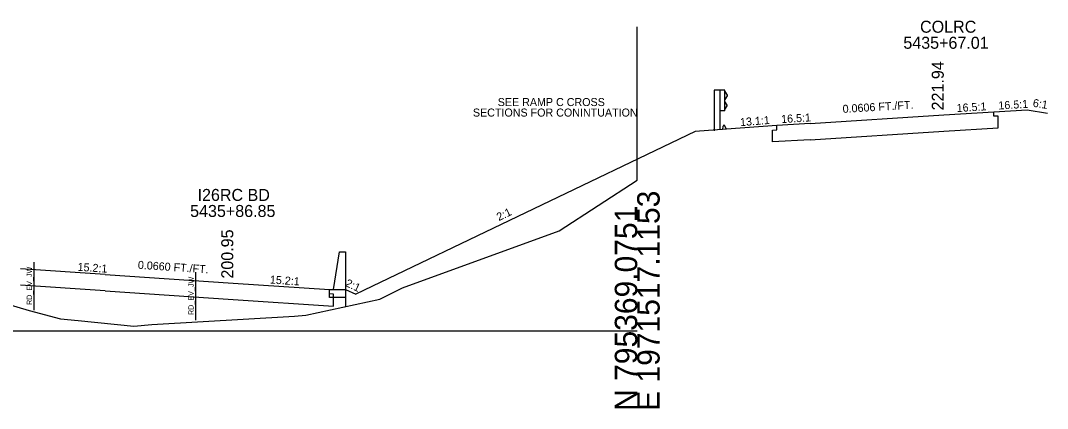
# Model space of a CAD drawing. Extents: x -161 to 1970889, y -4362 to 797231.
# Drawn here: x 1223 to 1351.2, y 2490.3 to 2538.7 of the extents above; entities that cross this region are included whole.
import ezdxf

# ---------------------------------------------------------------- set-up
doc = ezdxf.new("R2010")
doc.units = 0
for name, color, linetype in [('RD_GPK_XS_Cell', 7, 'Continuous'), ('RD_XS_Base', 7, 'Continuous'), ('RD_XS_Box', 7, 'Continuous'), ('RD_XS_CurbTop', 7, 'Continuous'), ('RD_XS_EarthShd', 7, 'Continuous'), ('RD_XS_ExGround', 7, 'Continuous'), ('RD_XS_EXWetland', 7, 'Continuous'), ('RD_XS_GR', 7, 'Continuous'), ('RD_XS_MedBWall', 7, 'Continuous'), ('RD_XS_Pave', 7, 'Continuous'), ('RD_XS_PaveShd', 7, 'Continuous'), ('RD_XS_TieSlope', 7, 'Continuous'), ('RD_XS_TX_Elev_PR', 7, 'Continuous'), ('RD_XS_TX_Notes', 7, 'Continuous'), ('RD_XS_TX_Profile', 7, 'Continuous'), ('RD_XS_TX_ShdSlope', 7, 'Continuous'), ('RD_XS_TX_Slope', 7, 'Continuous'), ('RD_XS_TX_Station', 7, 'Continuous')]:
    doc.layers.add(name, color=color, linetype=linetype)

msp = doc.modelspace()

# ---------------------------------------------------------------- linework, layer by layer
at = {"layer": 'RD_GPK_XS_Cell'}
msp.add_line((1150, 2500), (1300, 2500), dxfattribs=at)
at = {"layer": 'RD_XS_Base'}
for p, q in [((1344.55, 2526.76), (1344.55, 2527.32)), ((1345.07, 2526.79), (1344.55, 2526.76)), ((1345.07, 2525.31), (1345.07, 2526.79)), ((1317.42, 2525.07), (1317.42, 2525.63)), ((1316.89, 2525.04), (1317.42, 2525.07)), ((1316.89, 2523.56), (1316.89, 2525.04)), ((1321.59, 2523.84), (1338.29, 2524.9)), ((1338.29, 2524.9), (1345.07, 2525.31)), ((1321.59, 2523.84), (1316.89, 2523.56)), ((1233.54, 2504.97), (1222.98, 2505.67)), ((1233.54, 2504.97), (1249.55, 2503.91)), ((1261.57, 2504.6), (1261.57, 2505.16)), ((1249.55, 2503.91), (1262.07, 2503.09)), ((1262.07, 2504.57), (1261.57, 2504.6)), ((1262.07, 2503.09), (1262.07, 2504.57))]:
    msp.add_line(p, q, dxfattribs=at)
at = {"layer": 'RD_XS_Box'}
for p, q in [((1261.57, 2505.16), (1263.57, 2505.16)), ((1263.57, 2505.16), (1263.57, 2503.01))]:
    msp.add_line(p, q, dxfattribs=at)
at = {"layer": 'RD_XS_CurbTop'}
for p, q in [((1310.68, 2525.11), (1310.74, 2525.55)), ((1311.15, 2525.15), (1310.9, 2525.6)), ((1311.15, 2525.15), (1310.68, 2525.11))]:
    msp.add_line(p, q, dxfattribs=at)
msp.add_ellipse((1310.83, 2525.52), major_axis=(0, 0.131), ratio=0.686, start_param=5.388101, end_param=7.661995, dxfattribs=at)
at = {"layer": 'RD_XS_EarthShd'}
for p, q in [((1344.55, 2527.32), (1348.72, 2527.57)), ((1317.42, 2525.63), (1311.15, 2525.15))]:
    msp.add_line(p, q, dxfattribs=at)
at = {"layer": 'RD_XS_ExGround'}
msp.add_lwpolyline([(1220.21, 2503.67), (1224.04, 2502.52), (1227.95, 2501.47), (1230.17, 2501.28), (1237.12, 2500.58), (1239.38, 2500.79), (1257.18, 2501.84), (1258.61, 2501.93), (1267.84, 2503.95), (1270.7, 2505.34), (1290.24, 2512.47), (1300, 2518.81)], dxfattribs=at)
at = {"layer": 'RD_XS_EXWetland'}
for p, q in [((1224.64, 2508.56), (1224.64, 2502.56)), ((1244.84, 2507.31), (1244.84, 2501.31))]:
    msp.add_line(p, q, dxfattribs=at)
at = {"layer": 'RD_XS_GR'}
for p, q in [((1310.3, 2530.02), (1309.63, 2530.02)), ((1309.63, 2530.02), (1309.63, 2524.97)), ((1310.96, 2530.02), (1310.3, 2530.02)), ((1310.3, 2530.02), (1310.3, 2525.08)), ((1310.96, 2527.45), (1310.96, 2530.02)), ((1310.96, 2529.86), (1311.23, 2529.42)), ((1311.23, 2529.42), (1311.23, 2529.31)), ((1311.23, 2529.31), (1310.96, 2528.87)), ((1311.23, 2528.17), (1310.96, 2528.61)), ((1310.96, 2527.62), (1311.23, 2528.06)), ((1311.23, 2528.06), (1311.23, 2528.17)), ((1310.96, 2527.45), (1310.3, 2527.45))]:
    msp.add_line(p, q, dxfattribs=at)
at = {"layer": 'RD_XS_MedBWall'}
for p, q in [((1262.07, 2505.16), (1262.82, 2509.83)), ((1262.82, 2509.83), (1263.57, 2509.83)), ((1263.57, 2509.83), (1263.57, 2504.16)), ((1261.57, 2504.16), (1261.57, 2505.16)), ((1261.57, 2505.16), (1262.07, 2505.16)), ((1263.57, 2504.16), (1261.57, 2504.16))]:
    msp.add_line(p, q, dxfattribs=at)
at = {"layer": 'RD_XS_Pave'}
for p, q in [((1321.59, 2525.88), (1338.29, 2526.94)), ((1233.54, 2507.01), (1249.55, 2505.95))]:
    msp.add_line(p, q, dxfattribs=at)
at = {"layer": 'RD_XS_PaveShd'}
for p, q in [((1338.29, 2526.94), (1344.55, 2527.32)), ((1321.59, 2525.88), (1317.42, 2525.63)), ((1233.54, 2507.01), (1222.98, 2507.71)), ((1249.55, 2505.95), (1261.57, 2505.16))]:
    msp.add_line(p, q, dxfattribs=at)
at = {"layer": 'RD_XS_TieSlope'}
for p, q in [((1348.72, 2527.57), (1351.24, 2527.17)), ((1307.23, 2524.85), (1264.84, 2504.57)), ((1311.15, 2525.15), (1307.23, 2524.85)), ((1263.57, 2505.16), (1264.84, 2504.57))]:
    msp.add_line(p, q, dxfattribs=at)
at = {"layer": 'RD_XS_TX_Notes'}
msp.add_line((1300, 2518.81), (1300, 2537.94), dxfattribs=at)

# ---------------------------------------------------------------- texts
at = {"layer": 'RD_GPK_XS_Cell'}
for s, p in [('E 1971517.1153', (1302.8, 2490)), ('N 795369.0751', (1300, 2490))]:
    msp.add_text(s, height=2.8, rotation=90, dxfattribs=at).set_placement(p)
at = {"layer": 'RD_XS_EXWetland'}
for p in [(1224.39, 2503.21), (1244.59, 2501.96)]:
    msp.add_text('RD_EV_JW', height=0.65, rotation=90, dxfattribs=at).set_placement(p)
at = {"layer": 'RD_XS_TX_Elev_PR'}
for s, p in [(' 221.94', (1338.29, 2526.94)), (' 200.95', (1249.55, 2505.95))]:
    msp.add_text(s, height=1.5, rotation=90, dxfattribs=at).set_placement(p)
at = {"layer": 'RD_XS_TX_Notes'}
for s, p in [('SEE RAMP C CROSS ', (1282.58, 2528.04)), ('SECTIONS FOR CONINTUATION', (1279.48, 2526.73))]:
    msp.add_text(s, height=1, rotation=360, dxfattribs=at).set_placement(p)
at = {"layer": 'RD_XS_TX_Profile'}
msp.add_text('15.2:1', height=1, rotation=356.2258, dxfattribs=at).set_placement((1254.1, 2505.9))
at = {"layer": 'RD_XS_TX_ShdSlope'}
for s, rotation, p in [('16.5:1', 3.4741, (1345.14, 2527.6)), ('13.1:1', 4.3785, (1312.88, 2525.53))]:
    msp.add_text(s, height=1, rotation=rotation, dxfattribs=at).set_placement(p)
at = {"layer": 'RD_XS_TX_Slope'}
for s, rotation, p in [('0.0606 FT./FT.', 3.4662, (1325.69, 2527.18)), ('16.5:1', 3.4741, (1339.93, 2527.29)), ('6:1', 350.9165, (1349.36, 2527.97)), ('16.5:1', 3.4662, (1318.01, 2525.91)), ('2:1', 25.5735, (1282.73, 2513.68)), ('15.2:1', 356.2257, (1230.08, 2507.49)), ('0.0660 FT./FT.', 356.2257, (1237.61, 2507.74)), ('2:1', 335.0046, (1263.46, 2505.61))]:
    msp.add_text(s, height=1, rotation=rotation, dxfattribs=at).set_placement(p)
at = {"layer": 'RD_XS_TX_Station'}
for s, p in [('COLRC', (1335.33, 2537.19)), ('5435+67.01', (1333.24, 2535.19)), ('I26RC BD', (1245.09, 2516.2)), ('5435+86.85', (1244.16, 2514.2))]:
    msp.add_text(s, height=1.5, dxfattribs=at).set_placement(p)

doc.saveas('drawing.dxf')
